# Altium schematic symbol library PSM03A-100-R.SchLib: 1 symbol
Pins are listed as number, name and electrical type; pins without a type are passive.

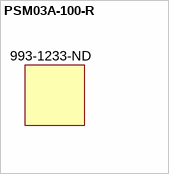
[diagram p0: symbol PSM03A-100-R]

## PSM03A-100-R
designator PS?  Supplier Part Number: 993-1233-ND
POWER SUPPLY WALL 10V 275MA 3W; Manufacturer: PHIHONG USA; SymbolVersion: use current date i.e. 2008-05-20; SymbolCreator: Use a-id; CompType: Used in some BOM reports.  Useful for finding later.; U/M: EA, IN, or GM; Cord Length: 59" (1.5m); Polarization: Positive Center; No Load Power Consumption: 150mW (Max); Approvals: cULus; Region Utilized: North America; Output Connector: Barrel Plug, 2.1mm I.D. x 5.5mm O.D. x 10.0mm; Efficiency: Level V; Form: Wall Mount; Voltage - Input: 90 ~ 264 VAC; Input Type: Fixed Blade
footprint PSMP03A-120-R (PHIHONG WALL WART 12V 230MA)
